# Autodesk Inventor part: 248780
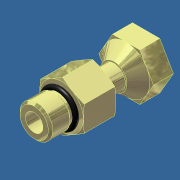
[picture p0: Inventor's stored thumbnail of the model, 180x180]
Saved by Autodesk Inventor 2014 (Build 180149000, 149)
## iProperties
Shininess: 20.0
Length Units: 11272
Angle Units: 11279
Time Units: 11290
Mass Units: 11286
Length Display Precision: 3
Angle Display Precision: 2
Company: Autodesk, Inc.
Created: 2001-12
Part Number: 248780
Material: Stainless Steel 316
Description: FITTING; ST-A9G20-(SS)
Document SubType Name: Modeling
Designer: Autodesk, Inc.
Density: 8.182 g/cm^3
Mass: 575.536 g
Surface Area: 264.194 cm^2
Volume: 70.3417 cm^3
Appearance: Stainless Steel
Density: 7.86
Volumn: 5.818506058552819
Area: 35.84085697721723
PropertySet Name: Model Information
Control State: 0
Master: False
Checked Out: False
Last Check In By: JT
Last Check In Date: 2003-06-20
MODEL - 1: ---
MODEL - 2: ---
RAW MATERIAL: --------
SCALE:: 1=??
SIZE: 00 x 00 x 00
SUB-ASSY - 1: ------
SUB-ASSY - 1 - QUA: 1
SUB-ASSY - 2: ------
SUB-ASSY - 2 - QUA: 1
SYM. TO:: N/A
TEMPLATE CREATION: -- / __-__-__
Title: FITTING; ST-A9G20-(SS)
Author: Autodesk, Inc.
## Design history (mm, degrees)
derived "ST-A9G.ipt"
body "Solid1"
tag "TaggingFeature2"
feature "Solid1::ST-A9G.ipt" dims "ScaleForDerivedMember" = 10
